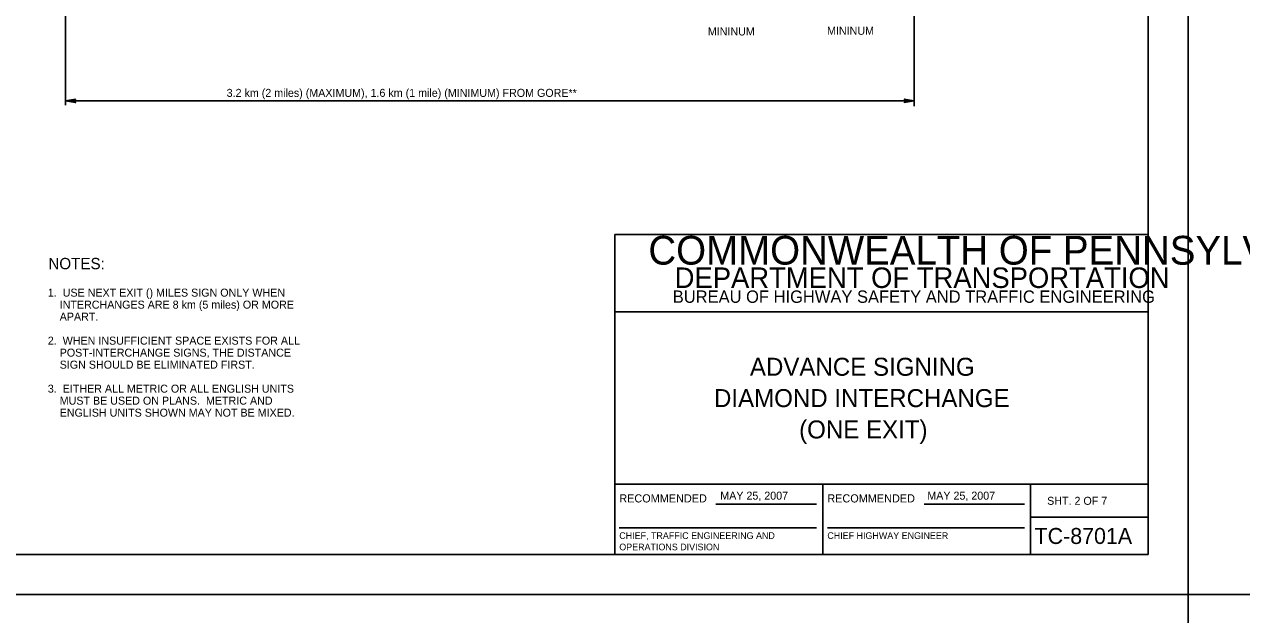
# Model space of a CAD drawing. Extents: x 640994 to 644422, y 298458 to 299646.
# Drawn here: x 642240 to 642696.3, y 299044.1 to 299265.4 of the extents above; entities that cross this region are included whole.
import ezdxf

# ---------------------------------------------------------------- set-up
doc = ezdxf.new("R2010")
doc.units = 0
for name, color, linetype in [('1', 7, 'Continuous'), ('2', 7, 'Continuous'), ('XCS-GRID-MIN', 7, 'Continuous')]:
    doc.layers.add(name, color=color, linetype=linetype)

msp = doc.modelspace()

# ---------------------------------------------------------------- linework, layer by layer
at = {"layer": '1'}
for p, q in [((642661.31, 299066.63), (642661.31, 299630.63)), ((642461.31, 299066.63), (642461.31, 299186.63)), ((642461.31, 299186.63), (642661.31, 299186.63)), ((642661.31, 299157.63), (642461.31, 299157.63)), ((642461.31, 299093), (642661.31, 299093)), ((642539.31, 299093), (642539.31, 299066.63)), ((642617.19, 299066.63), (642617.19, 299093)), ((642499.24, 299085.57), (642536.87, 299085.57)), ((642577.24, 299085.57), (642614.87, 299085.57)), ((642617.19, 299080.63), (642661.31, 299080.63)), ((642462.99, 299076.68), (642536.87, 299076.68)), ((642540.99, 299076.68), (642614.87, 299076.68)), ((642661.31, 299066.63), (641875.31, 299066.63)), ((641875.31, 299066.63), (642461.31, 299066.63))]:
    msp.add_line(p, q, dxfattribs=at)
at = {"layer": '2'}
for p, q in [((642573.56, 299352.88), (642573.56, 299234.75)), ((642255.44, 299338.75), (642255.44, 299235.13)), ((642573.56, 299236.75), (642255.44, 299236.75))]:
    msp.add_line(p, q, dxfattribs=at)
for points in [[(642258.94, 299236.25), (642258.81, 299236.5), (642255.44, 299236.75), (642258.94, 299236.25), (642259.19, 299236.13), (642255.44, 299236.75), (642258.81, 299236.88), (642258.94, 299237.13), (642255.44, 299236.75), (642259.19, 299237.38), (642258.94, 299237.13)], [(642570.06, 299237.25), (642570.19, 299237), (642573.56, 299236.75), (642570.06, 299237.25), (642569.81, 299237.38), (642573.56, 299236.75), (642570.19, 299236.63), (642570.06, 299236.38), (642573.56, 299236.75), (642569.81, 299236.13), (642570.06, 299236.38)]]:
    msp.add_lwpolyline(points, dxfattribs=at)
at = {"layer": 'XCS-GRID-MIN'}
for points in [[(641835.31, 299645.63), (642676.31, 299645.63), (642676.31, 299051.63), (641835.31, 299051.63)], [(642676.31, 299645.63), (643517.31, 299645.63), (643517.31, 299051.63), (642676.31, 299051.63)], [(641835.31, 299051.63), (642676.31, 299051.63), (642676.31, 298457.63), (641835.31, 298457.63)], [(642676.31, 299051.63), (643517.31, 299051.63), (643517.31, 298457.63), (642676.31, 298457.63)]]:
    msp.add_lwpolyline(points, close=True, dxfattribs=at)

# ---------------------------------------------------------------- texts
at = {"layer": '1'}
for s, height, p in [('COMMONWEALTH OF PENNSYLVANIA', 10.7828, (642473.9, 299175.36)), ('DEPARTMENT OF TRANSPORTATION', 7.6837, (642483.76, 299166.61)), ('BUREAU OF HIGHWAY SAFETY AND TRAFFIC ENGINEERING', 4.6253, (642483.04, 299161.04)), ('ADVANCE SIGNING', 6.75, (642511.96, 299133.69)), ('DIAMOND INTERCHANGE', 6.75, (642498.49, 299121.94)), ('(ONE EXIT)', 6.75, (642530.41, 299110.19)), ('RECOMMENDED', 3.048, (642462.99, 299086.2)), ('RECOMMENDED', 3.048, (642540.99, 299086.2)), ('SHT. 2 OF 7', 3, (642623.4, 299085.31)), ('CHIEF, TRAFFIC ENGINEERING AND', 2.5, (642462.99, 299072.51)), ('CHIEF HIGHWAY ENGINEER', 2.5, (642540.99, 299072.51)), ('TC-8701A', 6, (642618.68, 299070.63)), ('OPERATIONS DIVISION', 2.5, (642462.99, 299068.26))]:
    msp.add_text(s, height=height, dxfattribs=at).set_placement(p)
at = {"layer": '2'}
for s, height, p in [(' MININUM', 3, (642495.07, 299261.28)), (' MININUM', 3, (642539.76, 299261.54)), ('3.2 km (2 miles) (MAXIMUM), 1.6 km (1 mile) (MINIMUM) FROM GORE**', 3, (642315.8, 299238.25)), ('NOTES:', 4.25, (642248.97, 299173.63)), ('1.  USE NEXT EXIT () MILES SIGN ONLY WHEN', 3, (642248.75, 299163.36)), ('    INTERCHANGES ARE 8 km (5 miles) OR MORE', 3, (642248.75, 299158.86)), ('    APART.', 3, (642248.75, 299154.36)), ('2.  WHEN INSUFFICIENT SPACE EXISTS FOR ALL', 3, (642248.75, 299145.36)), ('    POST-INTERCHANGE SIGNS, THE DISTANCE', 3, (642248.75, 299140.86)), ('    SIGN SHOULD BE ELIMINATED FIRST.', 3, (642248.75, 299136.36)), ('3.  EITHER ALL METRIC OR ALL ENGLISH UNITS', 3, (642248.75, 299127.36)), ('    MUST BE USED ON PLANS.  METRIC AND', 3, (642248.75, 299122.86)), ('    ENGLISH UNITS SHOWN MAY NOT BE MIXED.', 3, (642248.75, 299118.36)), ('MAY 25, 2007', 3, (642500.85, 299087.24))]:
    msp.add_text(s, height=height, dxfattribs=at).set_placement(p)
msp.add_text('MAY 25, 2007', height=3, rotation=360, dxfattribs=at).set_placement((642578.47, 299087.24))

doc.saveas('drawing.dxf')
